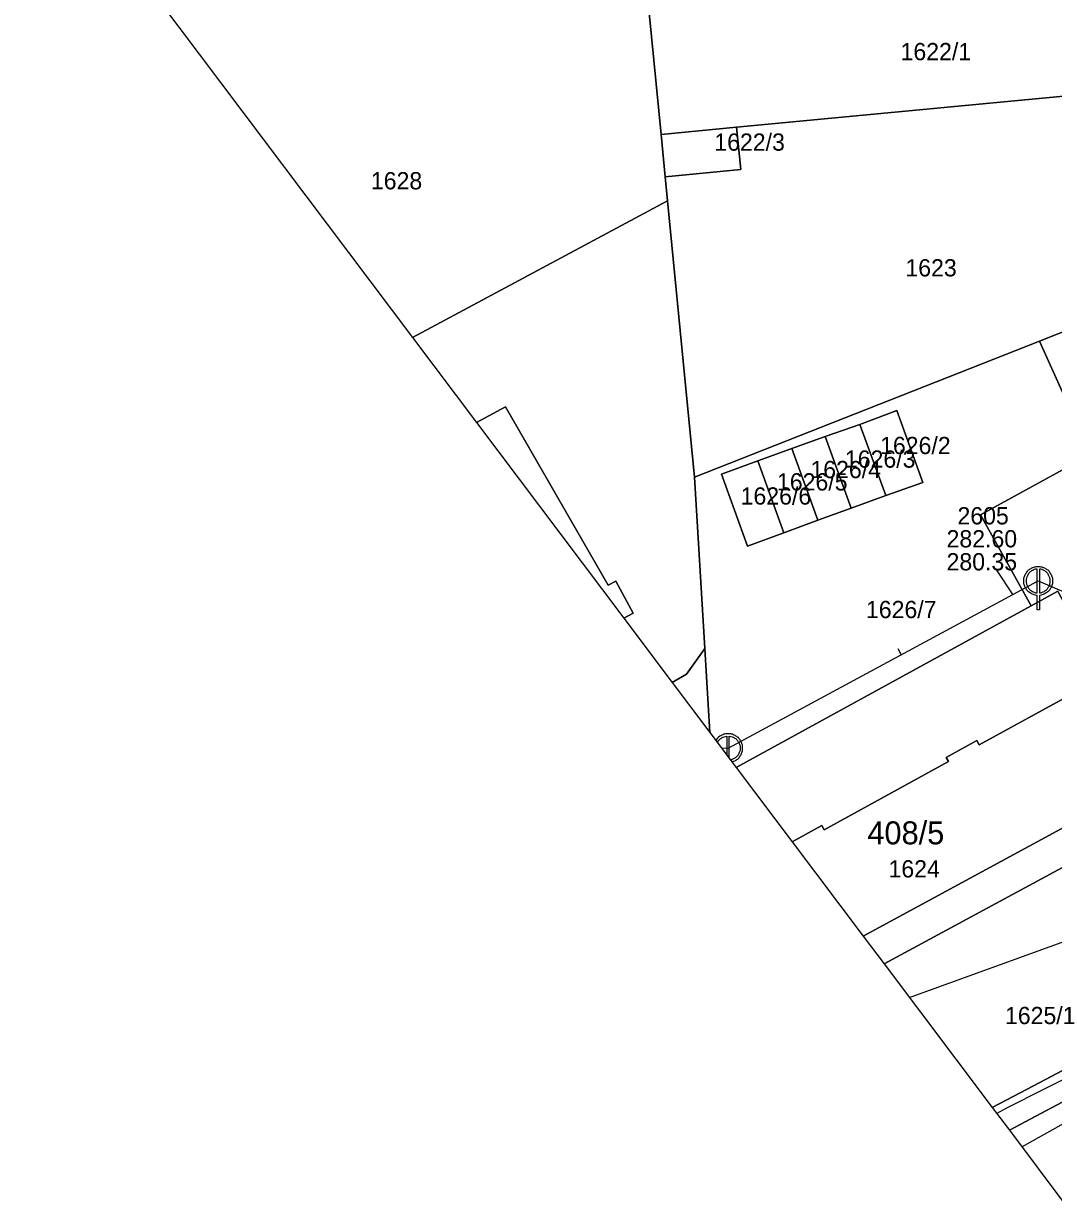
# Model space of a CAD drawing. Extents: x -570698 to -570232, y -1086952 to -1086596.
# Drawn here: x -570630.2 to -570540.7, y -1086876.1 to -1086773.3 of the extents above; entities that cross this region are included whole.
import ezdxf

# ---------------------------------------------------------------- set-up
doc = ezdxf.new("R2010")
doc.units = 0
for name, color, linetype in [('Adresní místo-text', 7, 'Continuous'), ('Default', 7, 'Continuous'), ('Kanalizační přípojka', 7, 'Continuous'), ('Kanalizační stoka', 7, 'Continuous'), ('Kanalizační šachta', 7, 'Continuous'), ('Parcela-polygon', 7, 'Continuous'), ('Parcela-text', 7, 'Continuous'), ('Popis šachty', 7, 'Continuous'), ('Vodovodní řad', 7, 'Continuous')]:
    doc.layers.add(name, color=color, linetype=linetype)

msp = doc.modelspace()

# ---------------------------------------------------------------- linework, layer by layer
at = {"layer": 'Default'}
for points in [[(-570542.08, -1086823.05), (-570542.34, -1086823.03), (-570542.6, -1086822.88), (-570542.9, -1086822.72), (-570543.07, -1086822.42), (-570543.23, -1086822.12), (-570543.23, -1086821.8), (-570543.23, -1086821.47), (-570543.06, -1086821.17), (-570542.89, -1086820.87), (-570542.6, -1086820.71), (-570542.3, -1086820.55), (-570541.98, -1086820.55), (-570541.67, -1086820.55), (-570541.37, -1086820.71), (-570541.07, -1086820.87), (-570540.9, -1086821.17), (-570540.73, -1086821.47), (-570540.73, -1086821.8), (-570540.73, -1086822.12), (-570540.89, -1086822.42), (-570541.06, -1086822.72), (-570541.36, -1086822.88), (-570541.62, -1086823.03), (-570541.88, -1086823.05)], [(-570542.08, -1086820.76), (-570542.28, -1086820.78), (-570542.5, -1086820.89), (-570542.74, -1086821.03), (-570542.88, -1086821.28), (-570543.02, -1086821.53), (-570543.02, -1086821.8), (-570543.02, -1086822.07), (-570542.89, -1086822.32), (-570542.75, -1086822.56), (-570542.5, -1086822.7), (-570542.29, -1086822.82), (-570542.08, -1086822.84)], [(-570541.88, -1086822.84), (-570541.67, -1086822.82), (-570541.46, -1086822.7), (-570541.21, -1086822.56), (-570541.07, -1086822.32), (-570540.94, -1086822.07), (-570540.94, -1086821.8), (-570540.94, -1086821.53), (-570541.08, -1086821.28), (-570541.22, -1086821.03), (-570541.47, -1086820.89), (-570541.68, -1086820.78), (-570541.88, -1086820.76)]]:
    msp.add_open_spline(points, degree=3, dxfattribs=at)
at = {"layer": 'Kanalizační přípojka'}
for points in [[(-570545.61, -1086820.87), (-570544.19, -1086822.99)], [(-570554.19, -1086827.66), (-570553.89, -1086828.22)], [(-570569.51, -1086836.32), (-570568.95, -1086836.33)]]:
    msp.add_lwpolyline(points, dxfattribs=at)
at = {"layer": 'Kanalizační stoka'}
for points in [[(-570568.95, -1086836.33), (-570541.98, -1086821.8)], [(-570541.98, -1086821.8), (-570539.34, -1086822.93)], [(-570553.19, -1086858), (-570553.03, -1086857.97), (-570535.9, -1086851.76)], [(-570543.41, -1086870.99), (-570537.54, -1086867.73), (-570518.46, -1086857.12)]]:
    msp.add_lwpolyline(points, dxfattribs=at)
at = {"layer": 'Kanalizační šachta'}
for p, q in [((-570569.05, -1086835.29), (-570569.05, -1086836.94)), ((-570568.85, -1086837.21), (-570568.85, -1086835.29)), ((-570570.01, -1086835.67), (-570569.87, -1086835.85)), ((-570569.05, -1086836.94), (-570568.85, -1086837.21)), ((-570568.74, -1086837.35), (-570568.6, -1086837.53))]:
    msp.add_line(p, q, dxfattribs=at)
for points in [[(-570542.08, -1086822.84), (-570542.08, -1086820.76)], [(-570541.88, -1086820.76), (-570541.88, -1086822.84)], [(-570541.88, -1086823.05), (-570541.88, -1086824.3), (-570542.08, -1086824.3), (-570542.08, -1086823.05)]]:
    msp.add_lwpolyline(points, dxfattribs=at)
for points in [[(-570568.6, -1086837.53), (-570568.47, -1086837.49), (-570568.33, -1086837.41), (-570568.03, -1086837.25), (-570567.86, -1086836.95), (-570567.7, -1086836.65), (-570567.7, -1086836.33), (-570567.7, -1086836), (-570567.87, -1086835.7), (-570568.04, -1086835.4), (-570568.34, -1086835.24), (-570568.64, -1086835.08), (-570568.95, -1086835.08), (-570569.27, -1086835.08), (-570569.57, -1086835.24), (-570569.84, -1086835.39), (-570570.01, -1086835.67)], [(-570569.87, -1086835.85), (-570569.86, -1086835.83), (-570569.85, -1086835.81), (-570569.71, -1086835.56), (-570569.47, -1086835.42), (-570569.25, -1086835.31), (-570569.05, -1086835.29)], [(-570568.85, -1086835.29), (-570568.65, -1086835.31), (-570568.44, -1086835.42), (-570568.19, -1086835.56), (-570568.05, -1086835.81), (-570567.91, -1086836.06), (-570567.91, -1086836.33), (-570567.91, -1086836.6), (-570568.04, -1086836.85), (-570568.18, -1086837.09), (-570568.43, -1086837.23), (-570568.59, -1086837.32), (-570568.74, -1086837.35)]]:
    msp.add_open_spline(points, degree=3, dxfattribs=at)
at = {"layer": 'Parcela-polygon'}
for p, q in [((-570630.23, -1086755.7), (-570596.4, -1086800.62)), ((-570596.4, -1086800.62), (-570590.83, -1086808.02)), ((-570590.83, -1086808.02), (-570578.02, -1086825.02)), ((-570578.02, -1086825.02), (-570573.81, -1086830.62)), ((-570573.81, -1086830.62), (-570570.53, -1086834.97)), ((-570570.53, -1086834.97), (-570568.24, -1086838.02)), ((-570568.24, -1086838.02), (-570563.38, -1086844.47)), ((-570563.38, -1086844.47), (-570557.2, -1086852.68)), ((-570557.2, -1086852.68), (-570555.37, -1086855.1)), ((-570555.37, -1086855.1), (-570545.98, -1086867.58)), ((-570545.98, -1086867.58), (-570544.49, -1086869.55)), ((-570544.49, -1086869.55), (-570539.57, -1086876.09))]:
    msp.add_line(p, q, dxfattribs=at)
for points in [[(-570291.64, -1086688.89), (-570302.37, -1086696.04), (-570396.95, -1086758.9), (-570417.85, -1086767.9), (-570426.99, -1086775.07), (-570430.55, -1086777.63), (-570432.81, -1086779.33), (-570437.1, -1086782.56), (-570450.62, -1086793.64), (-570452.87, -1086797.51), (-570456.3, -1086803.42), (-570469.27, -1086814.47), (-570499.22, -1086840.17), (-570503.94, -1086844.12), (-570508.33, -1086847.72), (-570512.7, -1086850.77), (-570519.4, -1086855.31), (-570522.96, -1086857.62), (-570528.66, -1086861.02), (-570535.32, -1086864.67), (-570544.49, -1086869.55)], [(-570596.4, -1086800.62), (-570574.22, -1086788.74), (-570574.42, -1086786.67), (-570574.78, -1086782.97), (-570576.24, -1086767.98), (-570576.71, -1086763.1), (-570575.63, -1086752.18), (-570575.16, -1086747.45), (-570598.86, -1086744.76), (-570630.23, -1086755.7)], [(-570573.81, -1086830.62), (-570572.56, -1086829.91), (-570570.98, -1086827.68), (-570571.88, -1086812.78), (-570574.22, -1086788.74), (-570596.4, -1086800.62)], [(-570544.49, -1086869.55), (-570535.32, -1086864.67), (-570528.66, -1086861.02), (-570522.96, -1086857.62), (-570519.4, -1086855.31), (-570512.7, -1086850.77), (-570508.33, -1086847.72), (-570503.94, -1086844.12), (-570499.22, -1086840.17), (-570469.27, -1086814.47), (-570456.3, -1086803.42), (-570452.87, -1086797.51), (-570485.9, -1086825.32), (-570492.12, -1086830.55), (-570513.86, -1086848.7), (-570520.15, -1086853.96), (-570542.94, -1086866), (-570545.98, -1086867.58)], [(-570568.24, -1086838.02), (-570542.59, -1086823.97), (-570547, -1086816.06), (-570537.68, -1086810.96), (-570533.06, -1086818.87), (-570532.7, -1086818.69), (-570537.33, -1086810.17), (-570537.63, -1086810.34), (-570541.87, -1086800.95), (-570571.88, -1086812.78), (-570570.98, -1086827.68), (-570570.53, -1086834.97)], [(-570578.02, -1086825.02), (-570577.22, -1086824.59), (-570578.72, -1086821.81), (-570579.38, -1086822.17), (-570588.32, -1086806.67), (-570590.83, -1086808.02)], [(-570590.83, -1086808.02), (-570588.32, -1086806.67), (-570579.38, -1086822.17), (-570578.72, -1086821.81), (-570577.22, -1086824.59), (-570578.02, -1086825.02)], [(-570552.02, -1086813.23), (-570555.23, -1086814.37), (-570558.24, -1086815.47), (-570561.14, -1086816.52), (-570564.09, -1086817.6), (-570567.26, -1086818.76), (-570569.54, -1086812.5), (-570566.36, -1086811.35), (-570563.41, -1086810.29), (-570560.52, -1086809.24), (-570557.49, -1086808.19), (-570554.28, -1086806.99), (-570552.02, -1086813.23)], [(-570545.98, -1086867.58), (-570542.94, -1086866), (-570520.15, -1086853.96), (-570513.86, -1086848.7), (-570535.84, -1086820.27), (-570533.06, -1086818.87), (-570537.68, -1086810.96), (-570547, -1086816.06), (-570542.59, -1086823.97), (-570540.28, -1086822.7), (-570540.19, -1086822.86), (-570530.15, -1086841.46), (-570555.37, -1086855.1)], [(-570555.37, -1086855.1), (-570530.15, -1086841.46), (-570540.19, -1086822.86), (-570540.28, -1086822.7), (-570542.59, -1086823.97), (-570568.24, -1086838.02)], [(-570570.53, -1086834.97), (-570570.98, -1086827.68), (-570572.56, -1086829.91), (-570573.81, -1086830.62)], [(-570557.2, -1086852.68), (-570534.15, -1086840.19), (-570536.44, -1086835.95), (-570534.86, -1086835.09), (-570537.78, -1086829.7), (-570539.36, -1086830.56), (-570538.84, -1086831.52), (-570547.11, -1086836.05), (-570547.31, -1086835.68), (-570549.98, -1086837.14), (-570549.78, -1086837.51), (-570560.59, -1086843.43), (-570560.8, -1086843.06), (-570563.38, -1086844.47)], [(-570563.38, -1086844.47), (-570560.8, -1086843.06), (-570560.59, -1086843.43), (-570549.78, -1086837.51), (-570549.98, -1086837.14), (-570547.31, -1086835.68), (-570547.11, -1086836.05), (-570538.84, -1086831.52), (-570539.36, -1086830.56), (-570537.78, -1086829.7), (-570534.86, -1086835.09), (-570536.44, -1086835.95), (-570534.15, -1086840.19), (-570557.2, -1086852.68)]]:
    msp.add_lwpolyline(points, dxfattribs=at)
for points in [[(-570538.98, -1086751.22), (-570541.1, -1086771.74), (-570576.24, -1086767.98), (-570574.78, -1086782.97), (-570568.21, -1086782.35), (-570534.55, -1086779.16), (-570535.32, -1086751.53)], [(-570534.28, -1086788.61), (-570534.47, -1086781.74), (-570534.55, -1086779.16), (-570568.21, -1086782.35), (-570567.83, -1086786.02), (-570574.42, -1086786.67), (-570574.22, -1086788.74), (-570571.88, -1086812.78), (-570541.87, -1086800.95), (-570534.03, -1086797.85)], [(-570574.78, -1086782.97), (-570574.42, -1086786.67), (-570567.83, -1086786.02), (-570568.21, -1086782.35)], [(-570516.14, -1086793.85), (-570529.58, -1086796.76), (-570534.03, -1086797.85), (-570541.87, -1086800.95), (-570537.63, -1086810.34), (-570537.33, -1086810.17), (-570532.7, -1086818.69), (-570524.97, -1086814.49), (-570525.69, -1086813.18), (-570517.3, -1086808.64), (-570516.59, -1086809.94), (-570509.92, -1086806.32), (-570504.9, -1086815.55), (-570502.28, -1086814.13), (-570509.28, -1086799.19), (-570515.9, -1086799.64)], [(-570557.49, -1086808.19), (-570555.23, -1086814.37), (-570552.02, -1086813.23), (-570554.28, -1086806.99)], [(-570560.52, -1086809.24), (-570558.24, -1086815.47), (-570555.23, -1086814.37), (-570557.49, -1086808.19)], [(-570563.41, -1086810.29), (-570561.14, -1086816.52), (-570558.24, -1086815.47), (-570560.52, -1086809.24)], [(-570566.36, -1086811.35), (-570564.09, -1086817.6), (-570561.14, -1086816.52), (-570563.41, -1086810.29)], [(-570569.54, -1086812.5), (-570567.26, -1086818.76), (-570564.09, -1086817.6), (-570566.36, -1086811.35)]]:
    msp.add_lwpolyline(points, close=True, dxfattribs=at)
at = {"layer": 'Vodovodní řad'}
msp.add_lwpolyline([(-570429.33, -1086757.94), (-570424.04, -1086777.75), (-570480.43, -1086823), (-570494.45, -1086835.8), (-570516.51, -1086852.78), (-570525.38, -1086857.88), (-570544.75, -1086867.64), (-570545.58, -1086868.11)], dxfattribs=at)

# ---------------------------------------------------------------- texts
at = {"layer": 'Adresní místo-text'}
msp.add_text('408/5', height=2, dxfattribs=at).set_placement((-570556.84, -1086844.7))
at = {"layer": 'Parcela-text'}
for s, p in [('1622/1', (-570553.95, -1086776.52)), ('1622/3', (-570570.15, -1086784.39)), ('1628', (-570600.02, -1086787.75)), ('1623', (-570553.53, -1086795.32)), ('1626/2', (-570555.73, -1086810.77)), ('1626/3', (-570558.79, -1086811.95)), ('1626/4', (-570561.79, -1086812.86)), ('1626/5', (-570564.7, -1086813.93)), ('1626/6', (-570567.86, -1086815.16)), ('1626/7', (-570556.96, -1086825.03)), ('1624', (-570555, -1086847.58)), ('1625/1', (-570544.87, -1086860.33))]:
    msp.add_text(s, height=1.5, dxfattribs=at).set_placement(p)
at = {"layer": 'Popis šachty'}
for s, p in [('2605', (-570549, -1086816.88)), ('282.60', (-570549.95, -1086818.88)), ('280.35', (-570549.95, -1086820.88))]:
    msp.add_text(s, height=1.5, dxfattribs=at).set_placement(p)

doc.saveas('drawing.dxf')
